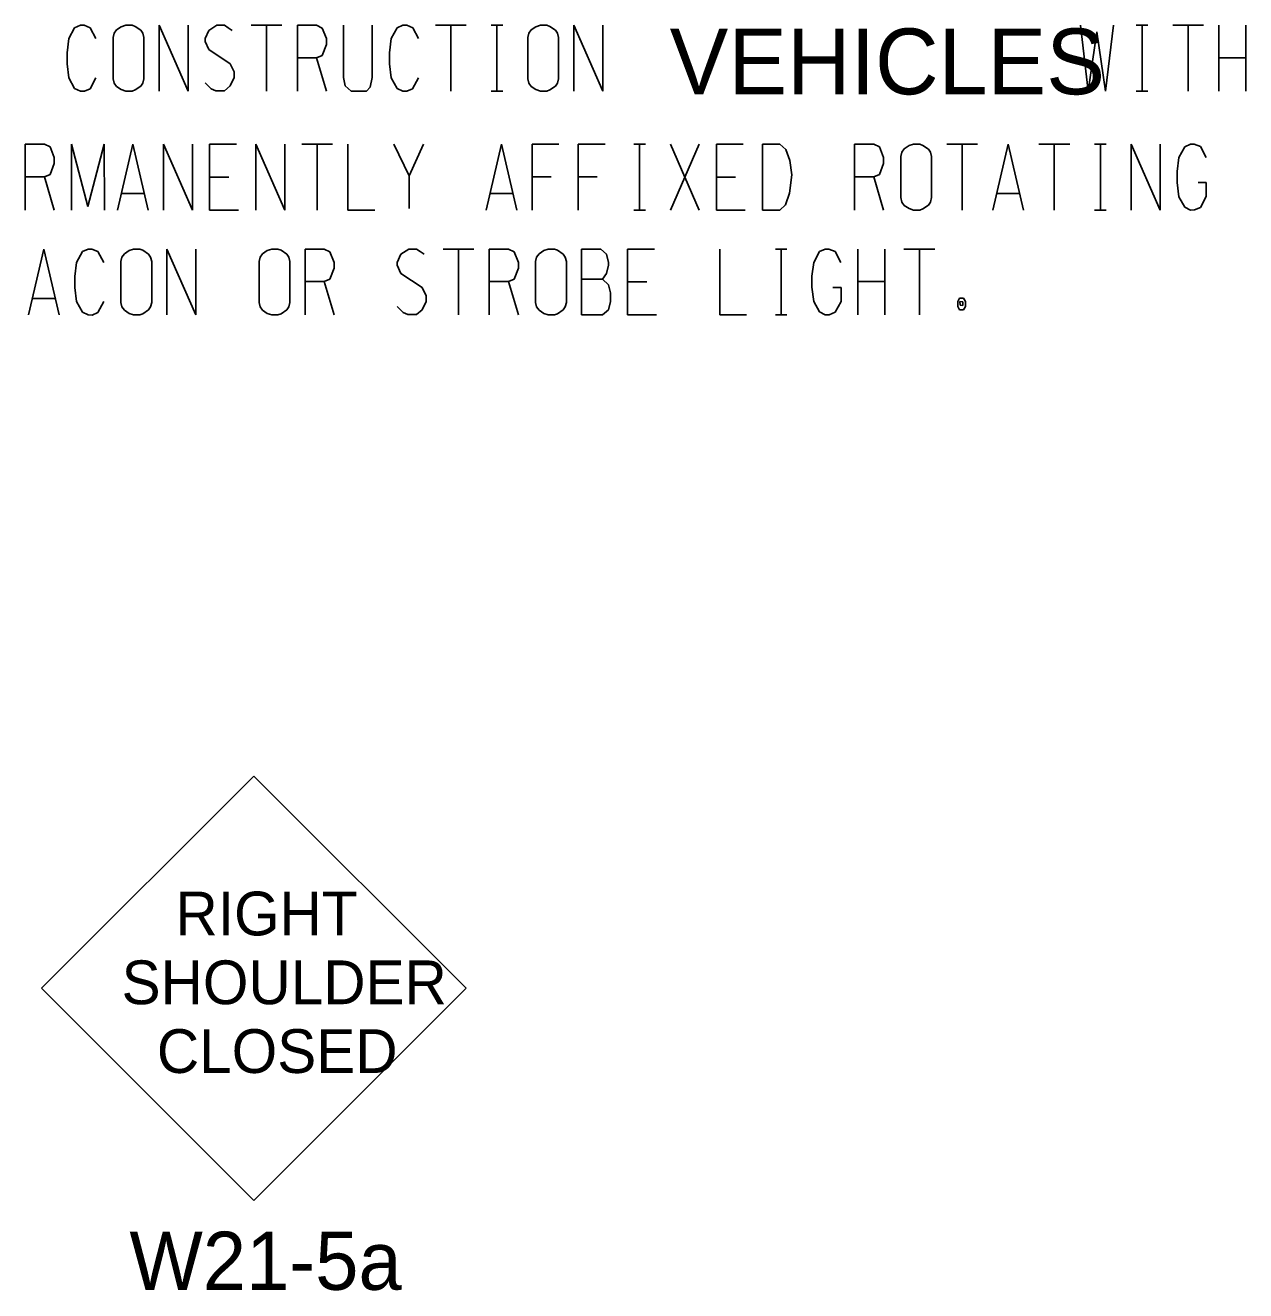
# Model space of a CAD drawing. Extents: x -1809 to 1557, y -1087 to 44.
# Drawn here: x -1243 to -1057.6, y -364.6 to -172.4 of the extents above; entities that cross this region are included whole.
import ezdxf

# ---------------------------------------------------------------- set-up
doc = ezdxf.new("R2010")
doc.units = 0
doc.layers.add('TRAFFIC_SIGNS_PR', color=7, linetype='Continuous')
doc.layers.add('TYPICAL_TEXT_DIMEN_EX', color=7, linetype='Continuous')

msp = doc.modelspace()

# ---------------------------------------------------------------- linework, layer by layer
at = {"layer": 'TRAFFIC_SIGNS_PR'}
for p, q in [((-1208.29, -286.43), (-1240.53, -318.67)), ((-1176.04, -318.67), (-1208.29, -286.43)), ((-1240.53, -318.67), (-1208.29, -350.92)), ((-1208.29, -350.92), (-1176.04, -318.67))]:
    msp.add_line(p, q, dxfattribs=at)
at = {"layer": 'TYPICAL_TEXT_DIMEN_EX'}
for p, q in [((-1235.51, -172.76), (-1236.41, -174.4)), ((-1234.64, -172.37), (-1235.51, -172.76)), ((-1234.06, -172.37), (-1234.64, -172.37)), ((-1233.14, -172.76), (-1234.06, -172.37)), ((-1232.27, -174.4), (-1233.14, -172.76)), ((-1229.14, -173.07), (-1228.42, -172.59)), ((-1228.42, -172.59), (-1227.73, -172.37)), ((-1227.73, -172.37), (-1226.79, -172.37)), ((-1226.79, -172.37), (-1226.33, -172.55)), ((-1226.33, -172.55), (-1225.45, -173.12)), ((-1222.68, -182.37), (-1222.68, -172.37)), ((-1222.68, -172.37), (-1218.27, -182.37)), ((-1218.27, -182.37), (-1218.27, -172.37)), ((-1213.93, -172.37), (-1215.13, -173.15)), ((-1212.75, -172.37), (-1213.93, -172.37)), ((-1212.18, -172.76), (-1212.75, -172.37)), ((-1212.18, -172.76), (-1211.6, -173.15)), ((-1208.68, -172.37), (-1204.01, -172.37)), ((-1206.35, -172.37), (-1206.35, -182.37)), ((-1201.68, -182.37), (-1201.68, -172.37)), ((-1201.68, -172.37), (-1198.76, -172.37)), ((-1198.76, -172.37), (-1197.89, -172.79)), ((-1197.89, -172.79), (-1197.27, -174.4)), ((-1194.68, -172.37), (-1194.68, -180.29)), ((-1190.31, -180.29), (-1190.31, -172.37)), ((-1186.51, -172.76), (-1187.41, -174.4)), ((-1185.64, -172.37), (-1186.51, -172.76)), ((-1185.06, -172.37), (-1185.64, -172.37)), ((-1184.14, -172.76), (-1185.06, -172.37)), ((-1183.27, -174.4), (-1184.14, -172.76)), ((-1180.68, -172.37), (-1176.01, -172.37)), ((-1178.35, -172.37), (-1178.35, -182.37)), ((-1172.22, -172.37), (-1170.47, -172.37)), ((-1171.35, -172.37), (-1171.35, -182.37)), ((-1166.14, -173.07), (-1165.42, -172.59)), ((-1165.42, -172.59), (-1164.73, -172.37)), ((-1164.73, -172.37), (-1163.79, -172.37)), ((-1163.79, -172.37), (-1163.33, -172.55)), ((-1163.33, -172.55), (-1162.45, -173.12)), ((-1159.68, -182.37), (-1159.68, -172.37)), ((-1159.68, -172.37), (-1155.27, -182.37)), ((-1155.27, -182.37), (-1155.27, -172.37)), ((-1082.68, -172.37), (-1081.51, -182.37)), ((-1078.89, -182.4), (-1077.67, -172.37)), ((-1074.22, -172.37), (-1072.47, -172.37)), ((-1073.35, -172.37), (-1073.35, -182.37)), ((-1068.68, -172.37), (-1064.01, -172.37)), ((-1066.35, -172.37), (-1066.35, -182.37)), ((-1061.68, -172.37), (-1061.68, -182.37)), ((-1057.6, -182.37), (-1057.6, -172.37)), ((-1236.41, -174.4), (-1236.66, -176.54)), ((-1229.65, -174.25), (-1229.5, -173.58)), ((-1229.65, -180.5), (-1229.65, -174.25)), ((-1229.5, -173.58), (-1229.14, -173.07)), ((-1225.45, -173.12), (-1225.14, -173.58)), ((-1225.14, -173.58), (-1224.99, -174.25)), ((-1224.99, -180.5), (-1224.99, -174.25)), ((-1215.66, -174.4), (-1215.67, -174.82)), ((-1215.67, -174.82), (-1215.12, -176.07)), ((-1215.13, -173.15), (-1215.66, -174.4)), ((-1197.27, -174.4), (-1197.27, -175.29)), ((-1187.41, -174.4), (-1187.66, -176.54)), ((-1166.65, -174.25), (-1166.5, -173.58)), ((-1166.65, -180.5), (-1166.65, -174.25)), ((-1166.5, -173.58), (-1166.14, -173.07)), ((-1162.45, -173.12), (-1162.14, -173.58)), ((-1162.14, -173.58), (-1161.99, -174.25)), ((-1161.99, -180.5), (-1161.99, -174.25)), ((-1081.51, -182.37), (-1080.19, -173.37)), ((-1080.19, -173.37), (-1078.89, -182.4)), ((-1236.66, -176.54), (-1236.66, -178.21)), ((-1215.12, -176.07), (-1211.87, -178.21)), ((-1197.27, -175.29), (-1197.89, -176.96)), ((-1187.66, -176.54), (-1187.66, -178.21)), ((-1236.66, -178.21), (-1236.41, -180.34)), ((-1211.28, -179.46), (-1211.87, -178.21)), ((-1198.76, -177.32), (-1201.68, -177.32)), ((-1197.89, -176.96), (-1198.76, -177.32)), ((-1198.76, -177.32), (-1197.27, -182.37)), ((-1187.66, -178.21), (-1187.41, -180.34)), ((-1061.68, -177.32), (-1057.6, -177.32)), ((-1236.41, -180.34), (-1235.51, -181.96)), ((-1232.27, -180.34), (-1233.16, -182.01)), ((-1229.65, -180.5), (-1229.5, -181.17)), ((-1225.14, -181.17), (-1224.99, -180.5)), ((-1211.87, -181.59), (-1211.28, -180.32)), ((-1211.28, -180.32), (-1211.28, -179.46)), ((-1194.41, -181.59), (-1194.68, -180.29)), ((-1190.31, -180.29), (-1190.6, -181.75)), ((-1187.41, -180.34), (-1186.51, -181.96)), ((-1183.27, -180.34), (-1184.16, -182.01)), ((-1166.65, -180.5), (-1166.5, -181.17)), ((-1162.14, -181.17), (-1161.99, -180.5)), ((-1235.51, -181.96), (-1234.64, -182.38)), ((-1234.64, -182.38), (-1234.04, -182.4)), ((-1234.04, -182.4), (-1233.16, -182.01)), ((-1229.5, -181.17), (-1229.14, -181.67)), ((-1229.14, -181.67), (-1228.42, -182.15)), ((-1228.42, -182.15), (-1227.73, -182.37)), ((-1227.73, -182.37), (-1226.79, -182.37)), ((-1226.79, -182.37), (-1226.33, -182.2)), ((-1226.33, -182.2), (-1225.45, -181.62)), ((-1225.45, -181.62), (-1225.14, -181.17)), ((-1215.68, -181.12), (-1214.79, -182.01)), ((-1214.79, -182.01), (-1214.06, -182.33)), ((-1214.06, -182.33), (-1212.76, -182.32)), ((-1212.76, -182.32), (-1211.87, -181.59)), ((-1193.51, -182.37), (-1194.41, -181.59)), ((-1191.18, -182.37), (-1193.51, -182.37)), ((-1190.6, -181.75), (-1191.18, -182.37)), ((-1186.51, -181.96), (-1185.64, -182.38)), ((-1185.64, -182.38), (-1185.04, -182.4)), ((-1185.04, -182.4), (-1184.16, -182.01)), ((-1172.22, -182.37), (-1170.47, -182.37)), ((-1166.5, -181.17), (-1166.14, -181.67)), ((-1166.14, -181.67), (-1165.42, -182.15)), ((-1165.42, -182.15), (-1164.73, -182.37)), ((-1164.73, -182.37), (-1163.79, -182.37)), ((-1163.79, -182.37), (-1163.33, -182.2)), ((-1163.33, -182.2), (-1162.45, -181.62)), ((-1162.45, -181.62), (-1162.14, -181.17)), ((-1074.22, -182.37), (-1072.47, -182.37)), ((-1243.01, -200.44), (-1243.01, -190.44)), ((-1243.01, -190.44), (-1240.09, -190.44)), ((-1240.09, -190.44), (-1239.22, -190.86)), ((-1239.22, -190.86), (-1238.6, -192.47)), ((-1236.01, -200.44), (-1236.01, -190.44)), ((-1236.01, -190.44), (-1233.49, -199.89)), ((-1233.49, -199.89), (-1231.01, -190.44)), ((-1231.01, -190.44), (-1231, -200.44)), ((-1229.01, -200.44), (-1226.68, -190.44)), ((-1226.68, -190.44), (-1224.34, -200.44)), ((-1222.01, -200.44), (-1222.01, -190.44)), ((-1222.01, -190.44), (-1217.6, -200.44)), ((-1217.6, -200.44), (-1217.6, -190.44)), ((-1210.93, -190.44), (-1215.01, -190.44)), ((-1215.01, -190.44), (-1215.01, -200.44)), ((-1208.01, -200.44), (-1208.01, -190.44)), ((-1208.01, -190.44), (-1203.6, -200.44)), ((-1203.6, -200.44), (-1203.6, -190.44)), ((-1201.01, -190.44), (-1196.34, -190.44)), ((-1198.68, -190.44), (-1198.68, -200.44)), ((-1194.01, -190.44), (-1194.01, -200.44)), ((-1187.01, -190.44), (-1184.68, -195.23)), ((-1184.68, -195.23), (-1182.49, -190.44)), ((-1173.01, -200.44), (-1170.68, -190.44)), ((-1170.68, -190.44), (-1168.34, -200.44)), ((-1161.93, -190.44), (-1166.01, -190.44)), ((-1166.01, -190.44), (-1166.01, -200.44)), ((-1154.93, -190.44), (-1159.01, -190.44)), ((-1159.01, -190.44), (-1159.01, -200.44)), ((-1150.55, -190.44), (-1148.8, -190.44)), ((-1149.68, -190.44), (-1149.68, -200.44)), ((-1145.01, -190.44), (-1140.63, -200.44)), ((-1140.63, -190.44), (-1145.01, -200.44)), ((-1133.93, -190.44), (-1138.01, -190.44)), ((-1138.01, -190.44), (-1138.01, -200.44)), ((-1128.38, -190.44), (-1131.01, -190.44)), ((-1131.01, -190.44), (-1131.01, -200.44)), ((-1128.38, -190.44), (-1127.47, -191.22)), ((-1127.47, -191.22), (-1126.87, -192.89)), ((-1117.01, -200.44), (-1117.01, -190.44)), ((-1117.01, -190.44), (-1114.09, -190.44)), ((-1114.09, -190.44), (-1113.22, -190.86)), ((-1113.22, -190.86), (-1112.6, -192.47)), ((-1109.98, -192.31), (-1109.82, -191.64)), ((-1109.82, -191.64), (-1109.47, -191.14)), ((-1109.47, -191.14), (-1108.75, -190.66)), ((-1108.75, -190.66), (-1108.05, -190.44)), ((-1108.05, -190.44), (-1107.12, -190.44)), ((-1107.12, -190.44), (-1106.66, -190.61)), ((-1106.66, -190.61), (-1105.78, -191.19)), ((-1105.78, -191.19), (-1105.47, -191.64)), ((-1105.47, -191.64), (-1105.31, -192.31)), ((-1103.01, -190.44), (-1098.34, -190.44)), ((-1100.68, -190.44), (-1100.68, -200.44)), ((-1096.01, -200.44), (-1093.68, -190.44)), ((-1093.68, -190.44), (-1091.34, -200.44)), ((-1089.01, -190.44), (-1084.34, -190.44)), ((-1086.68, -190.44), (-1086.68, -200.44)), ((-1080.55, -190.44), (-1078.8, -190.44)), ((-1079.68, -190.44), (-1079.68, -200.44)), ((-1075.01, -200.44), (-1075.01, -190.44)), ((-1075.01, -190.44), (-1070.6, -200.44)), ((-1070.6, -200.44), (-1070.6, -190.44)), ((-1066.84, -190.83), (-1067.74, -192.47)), ((-1065.98, -190.44), (-1066.84, -190.83)), ((-1065.44, -190.44), (-1065.98, -190.44)), ((-1064.47, -190.8), (-1065.44, -190.44)), ((-1063.6, -192.47), (-1064.47, -190.8)), ((-1238.6, -193.36), (-1239.22, -195.02)), ((-1238.6, -192.47), (-1238.6, -193.36)), ((-1126.87, -192.89), (-1126.55, -195.1)), ((-1112.6, -193.36), (-1113.22, -195.02)), ((-1112.6, -192.47), (-1112.6, -193.36)), ((-1109.98, -198.56), (-1109.98, -192.31)), ((-1105.31, -198.56), (-1105.31, -192.31)), ((-1067.74, -192.47), (-1067.99, -194.58)), ((-1240.09, -195.39), (-1243.01, -195.39)), ((-1239.22, -195.02), (-1240.09, -195.39)), ((-1240.09, -195.39), (-1238.6, -200.44)), ((-1212.09, -195.44), (-1215.01, -195.44)), ((-1184.68, -200.23), (-1184.68, -195.15)), ((-1166.01, -195.39), (-1163.11, -195.39)), ((-1159.01, -195.39), (-1156.11, -195.39)), ((-1135.09, -195.44), (-1138.01, -195.44)), ((-1126.55, -195.1), (-1126.91, -197.86)), ((-1114.09, -195.39), (-1117.01, -195.39)), ((-1113.22, -195.02), (-1114.09, -195.39)), ((-1114.09, -195.39), (-1112.6, -200.44)), ((-1067.99, -194.58), (-1067.99, -196.25)), ((-1224.93, -197.94), (-1228.43, -197.94)), ((-1168.93, -197.94), (-1172.43, -197.94)), ((-1126.91, -197.86), (-1127.51, -199.63)), ((-1091.93, -197.94), (-1095.43, -197.94)), ((-1067.99, -196.25), (-1067.74, -198.41)), ((-1064.8, -196.27), (-1063.58, -196.27)), ((-1063.58, -196.27), (-1063.58, -198.38)), ((-1127.51, -199.63), (-1128.38, -200.44)), ((-1109.98, -198.56), (-1109.82, -199.24)), ((-1109.82, -199.24), (-1109.47, -199.74)), ((-1109.47, -199.74), (-1108.75, -200.22)), ((-1106.66, -200.26), (-1105.78, -199.69)), ((-1105.78, -199.69), (-1105.47, -199.24)), ((-1105.47, -199.24), (-1105.31, -198.56)), ((-1067.74, -198.41), (-1066.86, -200)), ((-1063.58, -198.38), (-1064.47, -200.05)), ((-1215.01, -200.44), (-1210.63, -200.44)), ((-1194.01, -200.44), (-1189.93, -200.44)), ((-1150.55, -200.44), (-1148.8, -200.44)), ((-1138.01, -200.44), (-1133.63, -200.44)), ((-1131.01, -200.44), (-1128.38, -200.44)), ((-1108.75, -200.22), (-1108.05, -200.44)), ((-1108.05, -200.44), (-1107.12, -200.44)), ((-1107.12, -200.44), (-1106.66, -200.26)), ((-1080.55, -200.44), (-1078.8, -200.44)), ((-1066.86, -200), (-1065.97, -200.44)), ((-1065.97, -200.44), (-1065.36, -200.43)), ((-1065.36, -200.43), (-1064.47, -200.05)), ((-1242.51, -216.37), (-1240.17, -206.37)), ((-1240.17, -206.37), (-1237.84, -216.37)), ((-1234.34, -206.76), (-1235.23, -208.4)), ((-1233.47, -206.37), (-1234.34, -206.76)), ((-1232.88, -206.37), (-1233.47, -206.37)), ((-1231.97, -206.76), (-1232.88, -206.37)), ((-1231.09, -208.4), (-1231.97, -206.76)), ((-1228.48, -208.25), (-1228.32, -207.58)), ((-1228.32, -207.58), (-1227.96, -207.07)), ((-1227.96, -207.07), (-1227.24, -206.59)), ((-1227.24, -206.59), (-1226.55, -206.37)), ((-1226.55, -206.37), (-1225.62, -206.37)), ((-1225.62, -206.37), (-1225.16, -206.55)), ((-1225.16, -206.55), (-1224.28, -207.12)), ((-1224.28, -207.12), (-1223.97, -207.58)), ((-1223.97, -207.58), (-1223.81, -208.25)), ((-1221.51, -216.37), (-1221.51, -206.37)), ((-1221.51, -206.37), (-1217.09, -216.37)), ((-1217.09, -216.37), (-1217.09, -206.37)), ((-1207.48, -208.25), (-1207.32, -207.58)), ((-1207.32, -207.58), (-1206.96, -207.07)), ((-1206.96, -207.07), (-1206.24, -206.59)), ((-1206.24, -206.59), (-1205.55, -206.37)), ((-1205.55, -206.37), (-1204.62, -206.37)), ((-1204.62, -206.37), (-1204.16, -206.55)), ((-1204.16, -206.55), (-1203.28, -207.12)), ((-1203.28, -207.12), (-1202.97, -207.58)), ((-1202.97, -207.58), (-1202.81, -208.25)), ((-1200.51, -206.37), (-1197.59, -206.37)), ((-1200.51, -216.37), (-1200.51, -206.37)), ((-1197.59, -206.37), (-1196.72, -206.79)), ((-1196.72, -206.79), (-1196.09, -208.4)), ((-1185.96, -207.15), (-1186.49, -208.4)), ((-1184.76, -206.37), (-1185.96, -207.15)), ((-1183.57, -206.37), (-1184.76, -206.37)), ((-1183.01, -206.76), (-1183.57, -206.37)), ((-1183.01, -206.76), (-1182.42, -207.15)), ((-1179.51, -206.37), (-1174.84, -206.37)), ((-1177.17, -206.37), (-1177.17, -216.37)), ((-1172.51, -206.37), (-1169.59, -206.37)), ((-1172.51, -216.37), (-1172.51, -206.37)), ((-1169.59, -206.37), (-1168.72, -206.79)), ((-1168.72, -206.79), (-1168.09, -208.4)), ((-1165.48, -208.25), (-1165.32, -207.58)), ((-1165.32, -207.58), (-1164.96, -207.07)), ((-1164.96, -207.07), (-1164.24, -206.59)), ((-1164.24, -206.59), (-1163.55, -206.37)), ((-1163.55, -206.37), (-1162.62, -206.37)), ((-1162.62, -206.37), (-1162.16, -206.55)), ((-1162.16, -206.55), (-1161.28, -207.12)), ((-1161.28, -207.12), (-1160.97, -207.58)), ((-1160.97, -207.58), (-1160.81, -208.25)), ((-1158.51, -206.37), (-1155.59, -206.37)), ((-1158.51, -206.37), (-1158.51, -216.37)), ((-1155.59, -206.37), (-1154.7, -207.13)), ((-1154.7, -207.13), (-1154.42, -208.43)), ((-1147.42, -206.37), (-1151.51, -206.37)), ((-1151.51, -206.37), (-1151.51, -216.37)), ((-1137.51, -206.37), (-1137.51, -216.37)), ((-1129.05, -206.37), (-1127.3, -206.37)), ((-1128.17, -206.37), (-1128.17, -216.37)), ((-1122.34, -206.76), (-1123.23, -208.4)), ((-1121.48, -206.37), (-1122.34, -206.76)), ((-1120.94, -206.37), (-1121.48, -206.37)), ((-1119.97, -206.74), (-1120.94, -206.37)), ((-1119.09, -208.4), (-1119.97, -206.74)), ((-1116.51, -206.37), (-1116.51, -216.37)), ((-1112.42, -216.37), (-1112.42, -206.37)), ((-1109.51, -206.37), (-1104.84, -206.37)), ((-1107.17, -206.37), (-1107.17, -216.37)), ((-1235.23, -208.4), (-1235.49, -210.54)), ((-1228.48, -214.5), (-1228.48, -208.25)), ((-1223.81, -214.5), (-1223.81, -208.25)), ((-1207.48, -214.5), (-1207.48, -208.25)), ((-1202.81, -214.5), (-1202.81, -208.25)), ((-1196.09, -209.29), (-1196.72, -210.96)), ((-1196.09, -208.4), (-1196.09, -209.29)), ((-1186.49, -208.4), (-1186.5, -208.82)), ((-1186.5, -208.82), (-1185.94, -210.07)), ((-1168.09, -209.29), (-1168.72, -210.96)), ((-1168.09, -208.4), (-1168.09, -209.29)), ((-1165.48, -214.5), (-1165.48, -208.25)), ((-1160.81, -214.5), (-1160.81, -208.25)), ((-1154.42, -208.8), (-1154.7, -210.07)), ((-1154.42, -208.43), (-1154.42, -208.8)), ((-1123.23, -208.4), (-1123.49, -210.51)), ((-1235.49, -210.54), (-1235.49, -212.21)), ((-1197.59, -211.32), (-1200.51, -211.32)), ((-1196.72, -210.96), (-1197.59, -211.32)), ((-1197.59, -211.32), (-1196.09, -216.37)), ((-1185.94, -210.07), (-1182.7, -212.21)), ((-1169.59, -211.32), (-1172.51, -211.32)), ((-1168.72, -210.96), (-1169.59, -211.32)), ((-1169.59, -211.32), (-1168.09, -216.37)), ((-1158.51, -210.96), (-1155.3, -210.96)), ((-1154.7, -210.07), (-1155.3, -210.96)), ((-1155.3, -210.96), (-1154.42, -211.82)), ((-1148.59, -211.37), (-1151.51, -211.37)), ((-1123.49, -210.51), (-1123.49, -212.18)), ((-1116.51, -211.32), (-1112.42, -211.32)), ((-1235.49, -212.21), (-1235.23, -214.34)), ((-1182.11, -213.46), (-1182.7, -212.21)), ((-1154.42, -211.82), (-1154.09, -213.04)), ((-1154.09, -213.04), (-1154.09, -214.32)), ((-1123.49, -212.18), (-1123.23, -214.34)), ((-1120.3, -212.21), (-1119.08, -212.21)), ((-1119.08, -212.21), (-1119.08, -214.32)), ((-1238.42, -213.87), (-1241.92, -213.87)), ((-1235.23, -214.34), (-1234.34, -215.96)), ((-1231.09, -214.34), (-1231.99, -216.01)), ((-1228.48, -214.5), (-1228.32, -215.17)), ((-1228.32, -215.17), (-1227.96, -215.67)), ((-1224.28, -215.62), (-1223.97, -215.17)), ((-1223.97, -215.17), (-1223.81, -214.5)), ((-1207.48, -214.5), (-1207.32, -215.17)), ((-1207.32, -215.17), (-1206.96, -215.67)), ((-1203.28, -215.62), (-1202.97, -215.17)), ((-1202.97, -215.17), (-1202.81, -214.5)), ((-1186.51, -215.12), (-1185.61, -216.01)), ((-1182.7, -215.59), (-1182.11, -214.32)), ((-1182.11, -214.32), (-1182.11, -213.46)), ((-1165.48, -214.5), (-1165.32, -215.17)), ((-1165.32, -215.17), (-1164.96, -215.67)), ((-1161.28, -215.62), (-1160.97, -215.17)), ((-1160.97, -215.17), (-1160.81, -214.5)), ((-1154.09, -214.32), (-1154.42, -215.62)), ((-1123.23, -214.34), (-1122.36, -215.93)), ((-1119.08, -214.32), (-1119.97, -215.98)), ((-1101.07, -213.85), (-1101.34, -214.32)), ((-1101.34, -214.32), (-1101.34, -214.71)), ((-1101.34, -214.71), (-1101.34, -215.12)), ((-1101.34, -215.12), (-1101.07, -215.59)), ((-1100.47, -213.85), (-1101.07, -213.85)), ((-1101.02, -214.35), (-1100.56, -214.37)), ((-1101, -214.9), (-1101.01, -214.36)), ((-1100.55, -214.92), (-1101, -214.9)), ((-1100.56, -214.37), (-1100.55, -214.92)), ((-1100.19, -214.32), (-1100.47, -213.85)), ((-1100.47, -215.59), (-1100.19, -215.12)), ((-1100.19, -214.71), (-1100.19, -214.32)), ((-1100.19, -215.12), (-1100.19, -214.71)), ((-1234.34, -215.96), (-1233.46, -216.38)), ((-1233.46, -216.38), (-1232.86, -216.4)), ((-1232.86, -216.4), (-1231.99, -216.01)), ((-1227.96, -215.67), (-1227.24, -216.15)), ((-1227.24, -216.15), (-1226.55, -216.37)), ((-1226.55, -216.37), (-1225.62, -216.37)), ((-1225.62, -216.37), (-1225.16, -216.2)), ((-1225.16, -216.2), (-1224.28, -215.62)), ((-1206.96, -215.67), (-1206.24, -216.15)), ((-1206.24, -216.15), (-1205.55, -216.37)), ((-1205.55, -216.37), (-1204.62, -216.37)), ((-1204.62, -216.37), (-1204.16, -216.2)), ((-1204.16, -216.2), (-1203.28, -215.62)), ((-1185.61, -216.01), (-1184.88, -216.33)), ((-1184.88, -216.33), (-1183.59, -216.32)), ((-1183.59, -216.32), (-1182.7, -215.59)), ((-1164.96, -215.67), (-1164.24, -216.15)), ((-1164.24, -216.15), (-1163.55, -216.37)), ((-1163.55, -216.37), (-1162.62, -216.37)), ((-1162.62, -216.37), (-1162.16, -216.2)), ((-1162.16, -216.2), (-1161.28, -215.62)), ((-1158.51, -216.37), (-1155.3, -216.37)), ((-1154.42, -215.62), (-1155.3, -216.37)), ((-1151.51, -216.37), (-1147.13, -216.37)), ((-1137.51, -216.37), (-1133.42, -216.37)), ((-1129.05, -216.37), (-1127.3, -216.37)), ((-1122.36, -215.93), (-1121.47, -216.37)), ((-1121.47, -216.37), (-1120.86, -216.36)), ((-1120.86, -216.36), (-1119.97, -215.98)), ((-1101.07, -215.59), (-1100.47, -215.59))]:
    msp.add_line(p, q, dxfattribs=at)

# ---------------------------------------------------------------- texts
at = {"layer": 'TRAFFIC_SIGNS_PR'}
for s, height, p in [('RIGHT', 6.65, (-1220.19, -310.65)), ('SHOULDER', 6.65, (-1228.38, -321.1)), ('CLOSED', 6.65, (-1223.02, -331.55)), ('W21-5a', 8.835, (-1227.19, -364.5))]:
    msp.add_text(s, height=height, dxfattribs=at).set_placement(p)
at = {"layer": 'TYPICAL_TEXT_DIMEN_EX'}
msp.add_text('VEHICLES', height=10, dxfattribs=at).set_placement((-1145.12, -182.86))

doc.saveas('drawing.dxf')
